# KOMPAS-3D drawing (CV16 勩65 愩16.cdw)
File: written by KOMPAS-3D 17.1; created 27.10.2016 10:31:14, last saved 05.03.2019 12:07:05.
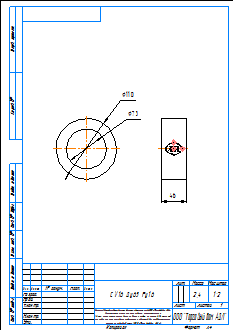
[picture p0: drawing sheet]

Sheet 1: A4, portrait

Title block, sheet 1: name: CV16 Ду65 Ру16; material: Сталь 20  ГОСТ 1050-88; mass: 2,4; sheets: 1; sheet format: A4; stored path: \\adlc.lan\data\АДЛ_ПКД\3D-модели\ADL production\Клапаны обратные ГРАНЛОК\CV16\KOMPAS 2D\CV16 Ду65 Ру16.cdw

Views: Вид 1, Проекционный вид 2
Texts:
  Klimkovich
  ADL
  Рама для чертежей
  Лит-Масса-Масштаб
  Материал-Предприятие
  Масштаб
  Изм.
  Лист
  № докум.
  Подп.
  Дата
  Лит.
  Разраб.
  Пров.
  Т.контр.
  Листов
  Внимание! Данный продукт является объектом авторского права ООО «Торговый Дом АДЛ».
  Запрещается изменение, копирование, распространение
  (в том числе путем копирования на другие сайты и ресурсы в Интернете)
  или любое иное использование информации и объектов без предварительного
  согласия правообладателя (ООО «Торговый Дом АДЛ»).
  Н.контр.
  Утв.
  ООО "Торговый дом АДЛ"
  Изменение
  Номер документа
  Подпись
  Обозначение документа
  Наименование изделия
  Масса изделия по ГОСТ 2.109-73
  Порядковый номер листа
  Общее количество листов в документе
  Характер работы, выполненной лицом, подписавшим документ
  Наименование или индекс предприятия, выпускающего документ
  Инв. № подл.
  Подп. и дата
  Взам. инв. №
  Инв. № дубл.
  Инвентарный номер подлинника по ГОСТ 2.501-68
  Подпись принявшего подлинник в отдел технической документации
  Инвентарный номер подлинника, взамен которого выпущен данный подлинник
  Инвентарный номер дубликата по ГОСТ 2.502-68
  Подпись принявшего дубликат в отдел технической документации
  Справ. №
  Перв. примен.
  Обозначение документа, взамен или на основании которого выпущен данный документ
  Обозначение документа, в котором впервые записан данный документ
  Подпись лица, копировавшего чертеж
  Обозначение формата листа
  !Рама для чертежа
Dimensions and other numbers on the sheet: 110; 73; 46; 1:2; 1; 2,4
